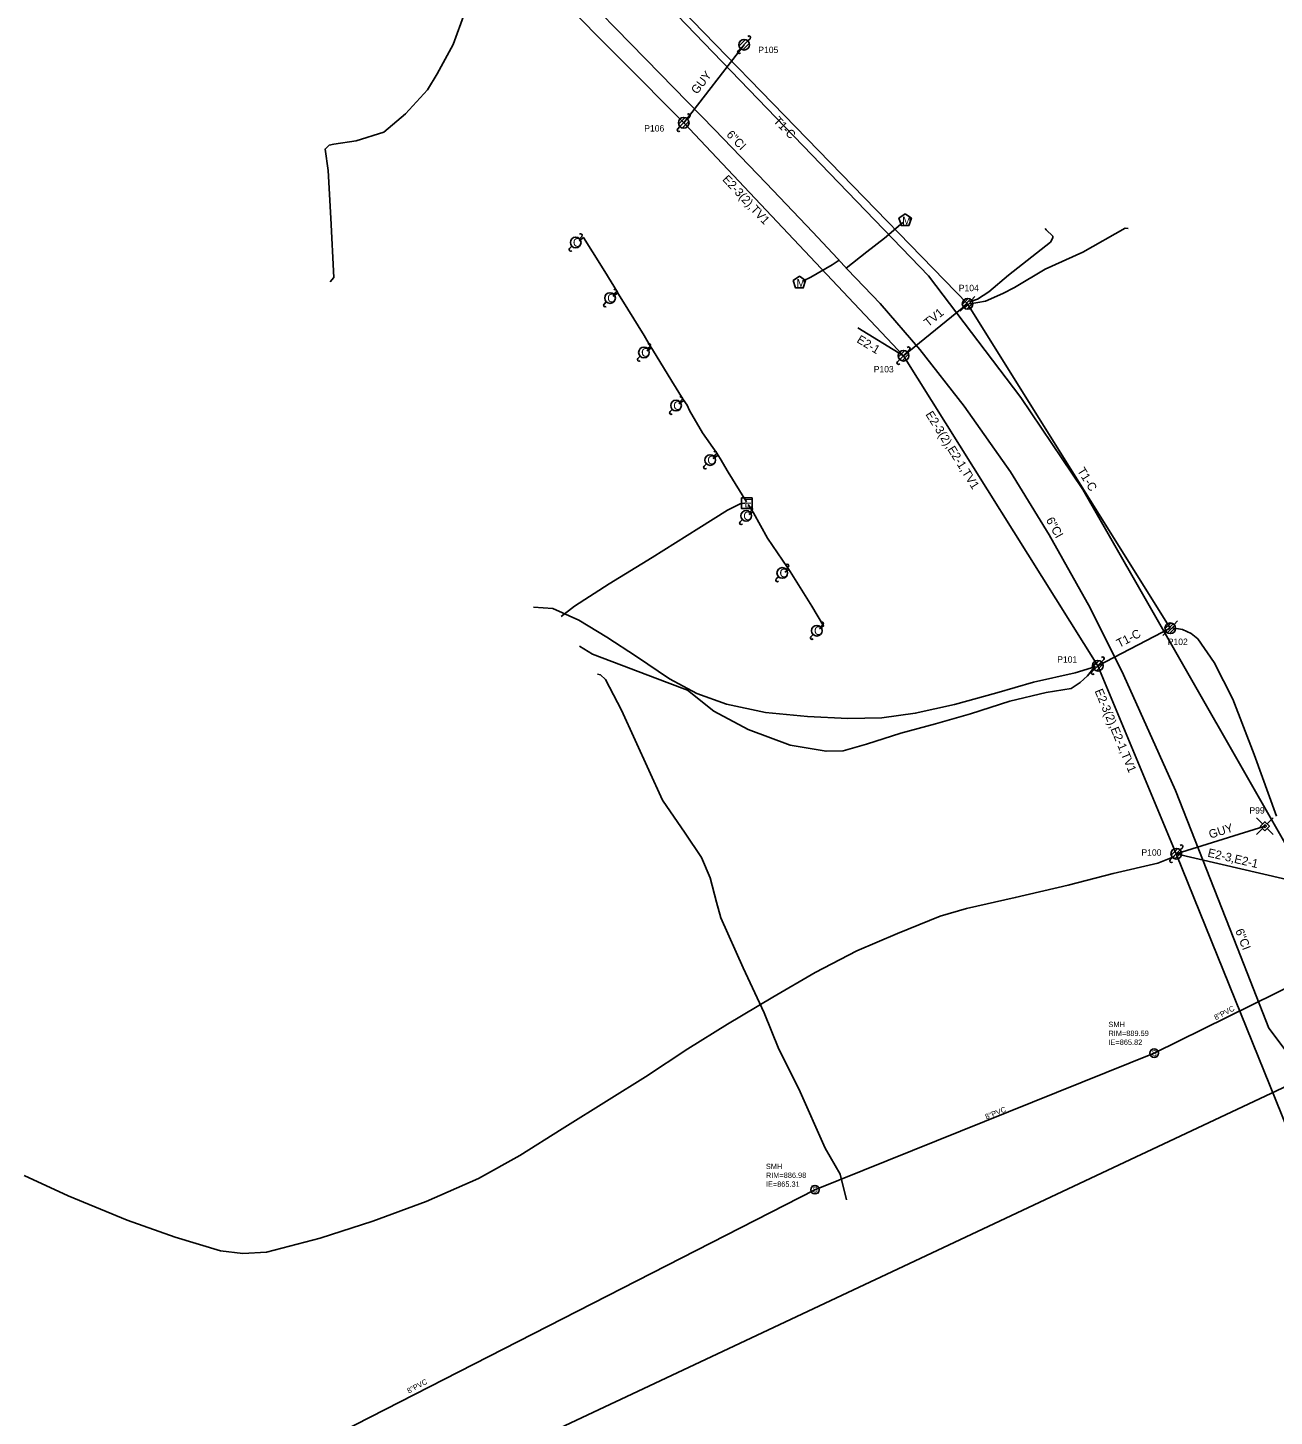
# Model space of a CAD drawing. Extents: x 1614474 to 1865144, y 1098877 to 1212550.
# Drawn here: x 1755426 to 1756010, y 1169393 to 1170044 of the extents above; entities that cross this region are included whole.
import ezdxf

# ---------------------------------------------------------------- set-up
doc = ezdxf.new("R2010")
doc.units = 0
for name, color, linetype in [('BFUSER_FIBERSPAN', 7, 'Continuous'), ('RD_EX_SU_Elec', 7, 'Continuous'), ('RD_EX_SU_H2O', 7, 'Continuous'), ('RD_EX_SU_Ovhd', 7, 'Continuous'), ('RD_EX_SU_Pole', 7, 'Continuous'), ('RD_EX_SU_Sewer', 7, 'Continuous'), ('RD_EX_SU_Telecom', 7, 'Continuous'), ('RD_EX_SU_TX_H2O', 7, 'Continuous'), ('RD_EX_SU_TX_Pole', 7, 'Continuous'), ('RD_EX_SU_TX_Sewer', 7, 'Continuous'), ('RD_EX_UT_txCode', 7, 'Continuous')]:
    doc.layers.add(name, color=color, linetype=linetype)

msp = doc.modelspace()

# ---------------------------------------------------------------- linework, layer by layer
at = {"layer": 'BFUSER_FIBERSPAN'}
msp.add_lwpolyline([(1758078.94, 1170569.49), (1756437.67, 1169746.37), (1754965.34, 1169053.6)], dxfattribs=at)
at = {"layer": 'RD_EX_SU_Elec'}
for p, q in [((1755702.73, 1169919.54), (1755700.29, 1169918.05)), ((1755718.36, 1169893.88), (1755716.17, 1169892.49)), ((1755733.63, 1169869.09), (1755731.28, 1169867.55)), ((1755749.51, 1169843.43), (1755747.2, 1169842.02)), ((1755765.88, 1169817.05), (1755763.94, 1169815.74)), ((1755782.68, 1169790.03), (1755780.92, 1169788.77))]:
    msp.add_line(p, q, dxfattribs=at)
for points in [[(1755684.46, 1169943.96), (1755686.55, 1169945.47), (1755690.71, 1169938.85), (1755696.53, 1169929.52), (1755702.44, 1169919.98), (1755703.01, 1169918.9), (1755707.36, 1169911.95), (1755714.97, 1169899.6), (1755717.94, 1169894.52), (1755718.91, 1169893.09), (1755727.93, 1169878.15), (1755733.31, 1169869.63), (1755735.09, 1169866.94), (1755736.27, 1169864.53), (1755742.27, 1169853.92), (1755748.95, 1169844.54), (1755750.51, 1169841.94), (1755754.3, 1169835.62), (1755762.89, 1169821.69)], [(1755676.08, 1169767.97), (1755682.39, 1169772.8), (1755698.54, 1169783.22), (1755718.76, 1169795.63), (1755740.54, 1169809.34), (1755754.04, 1169817.71), (1755760.01, 1169820.66), (1755762.08, 1169821.07)], [(1755763.74, 1169820.48), (1755766.13, 1169816.48), (1755772.7, 1169804.7), (1755782.19, 1169790.88), (1755783.33, 1169789.02), (1755793.45, 1169772.76), (1755799.06, 1169763.55), (1755797.19, 1169762.2)], [(1755684.66, 1169754.04), (1755690.84, 1169750.23), (1755725.82, 1169737.05), (1755735.31, 1169733.4), (1755747.58, 1169723.54), (1755763.77, 1169715.02), (1755783.44, 1169707.72), (1755800.18, 1169704.81), (1755808.23, 1169704.95), (1755819.09, 1169708.17), (1755835.24, 1169713.33), (1755851.43, 1169717.64), (1755867.91, 1169722.34), (1755886.25, 1169728.34), (1755903.35, 1169732.37), (1755915.01, 1169734.24), (1755919.17, 1169737), (1755922.6, 1169740.19), (1755926.26, 1169744.59)], [(1755693.13, 1169740.9), (1755694.52, 1169740.57), (1755696.86, 1169738.41), (1755704.43, 1169724), (1755723.64, 1169681.89), (1755734.14, 1169666.38), (1755741.88, 1169655), (1755745.97, 1169645.56), (1755748.9, 1169634.05), (1755750.96, 1169626.69), (1755761.42, 1169603.36), (1755771.14, 1169582.29), (1755778.12, 1169565.15), (1755787.43, 1169546.62), (1755799.74, 1169518.82), (1755806.76, 1169506.63), (1755809.83, 1169494.65)], [(1755424.52, 1169506.03), (1755445.15, 1169496.49), (1755472.72, 1169485.1), (1755495.28, 1169477.08), (1755516.56, 1169470.72), (1755526.98, 1169469.49), (1755538.07, 1169470.13), (1755563.21, 1169476.63), (1755587.94, 1169484.68), (1755612.91, 1169493.83), (1755637.34, 1169504.53), (1755656.67, 1169515.44), (1755676.53, 1169527.92), (1755698.61, 1169541.65), (1755715.55, 1169552.18), (1755735.48, 1169565.31), (1755754.08, 1169576.9), (1755775.19, 1169589.51), (1755795.14, 1169601.1), (1755814.55, 1169611.22), (1755833.58, 1169619.46), (1755853.58, 1169627.54), (1755865.92, 1169631.07), (1755888.79, 1169636.25), (1755913.59, 1169642.05), (1755934.73, 1169647.46), (1755955.57, 1169652.35), (1755963.38, 1169655.46)]]:
    msp.add_lwpolyline(points, dxfattribs=at)
msp.add_lwpolyline([(1755765.6, 1169823.52), (1755760.6, 1169823.52), (1755760.6, 1169818.52), (1755765.6, 1169818.52)], close=True, dxfattribs=at)
at = {"layer": 'RD_EX_SU_H2O'}
for points in [[(1755419.51, 1170324.82), (1755428.9, 1170315.01), (1755440.94, 1170302.99), (1755442.22, 1170301.65), (1755453.83, 1170289.61), (1755469.55, 1170274.72), (1755490.11, 1170254.98), (1755522.61, 1170222.9), (1755545.21, 1170201.07), (1755581.64, 1170164.83), (1755584.47, 1170162.08), (1755603.36, 1170143.23), (1755654.48, 1170091.61), (1755673.95, 1170071.98), (1755722.41, 1170022.15)], [(1755722.41, 1170022.15), (1755747.86, 1169996.13), (1755772.15, 1169970.92), (1755794.02, 1169947.98), (1755805.57, 1169935.7), (1755810.22, 1169930.6), (1755825.58, 1169914.6), (1755844.07, 1169892.99), (1755864.94, 1169866.54), (1755886.55, 1169835.77), (1755904.63, 1169806.26), (1755923.91, 1169771.92)], [(1755923.91, 1169771.92), (1755939.52, 1169740.59), (1755963.83, 1169686.41), (1755992.89, 1169612.51), (1756007.59, 1169575.08), (1756015.28, 1169564.93), (1756064.58, 1169585.92), (1756121.11, 1169611.4), (1756206.64, 1169653.11), (1756271, 1169684.14), (1756275.23, 1169686.24), (1756334.12, 1169715.1), (1756393.44, 1169745.19), (1756482.23, 1169790.32), (1756557.26, 1169827.38), (1756623.37, 1169859.51), (1756626.48, 1169861.14), (1756714.89, 1169903.8), (1756780.35, 1169935.86), (1756860.71, 1169974.61), (1756869.54, 1169979.15), (1756904.9, 1169996.7)], [(1755809.67, 1169931.2), (1755819.29, 1169938.73), (1755827.52, 1169945.25), (1755836.19, 1169952.51)], [(1755789.16, 1169925.01), (1755793.05, 1169926.98), (1755803.11, 1169932.73), (1755806.28, 1169934.92)]]:
    msp.add_lwpolyline(points, dxfattribs=at)
for points in [[(1755837.24, 1169956.61), (1755834.34, 1169954.51), (1755835.45, 1169951.1), (1755839.03, 1169951.1), (1755840.14, 1169954.51)], [(1755787.68, 1169927.44), (1755784.78, 1169925.33), (1755785.89, 1169921.92), (1755789.47, 1169921.92), (1755790.58, 1169925.33)]]:
    msp.add_lwpolyline(points, close=True, dxfattribs=at)
at = {"layer": 'RD_EX_SU_Ovhd'}
for p, q in [((1755579.05, 1170154.72), (1755733.5, 1169999.29)), ((1755667.78, 1170119.23), (1755866.5, 1169914.45)), ((1755733.5, 1169999.29), (1755761.81, 1170035.84)), ((1755866.5, 1169914.45), (1755961.43, 1169762.41)), ((1755815.1, 1169903.12), (1755836.46, 1169890.14)), ((1755836.46, 1169890.14), (1755927.48, 1169744.89)), ((1755927.48, 1169744.89), (1755961.43, 1169762.41)), ((1755927.48, 1169744.89), (1755964.26, 1169656.78)), ((1755964.26, 1169656.78), (1756005.76, 1169669.68)), ((1755964.26, 1169656.78), (1756027.03, 1169642.15)), ((1755964.26, 1169656.78), (1756076.65, 1169378.21))]:
    msp.add_line(p, q, dxfattribs=at)
for points in [[(1755733.5, 1169999.29), (1755836.46, 1169890.14)], [(1755836.46, 1169890.14), (1755866.5, 1169914.45)]]:
    msp.add_lwpolyline(points, dxfattribs=at)
at = {"layer": 'RD_EX_SU_Pole'}
for p, q in [((1755758.98, 1170033.01), (1755760.04, 1170034.07)), ((1755759.39, 1170035.19), (1755762.45, 1170038.25)), ((1755760.04, 1170034.07), (1755763.57, 1170037.61)), ((1755761.16, 1170033.42), (1755764.22, 1170036.48)), ((1755763.57, 1170037.61), (1755764.64, 1170038.67)), ((1755731.09, 1169998.65), (1755734.15, 1170001.71)), ((1755731.74, 1169997.53), (1755735.27, 1170001.06)), ((1755732.86, 1169996.88), (1755735.92, 1169999.94)), ((1755735.27, 1170001.06), (1755736.33, 1170002.12)), ((1755730.68, 1169996.47), (1755731.74, 1169997.53)), ((1755680.07, 1169940.36), (1755681.13, 1169941.43)), ((1755684.67, 1169944.96), (1755685.73, 1169946.02)), ((1755696.18, 1169914.32), (1755697.24, 1169915.38)), ((1755700.77, 1169918.92), (1755701.83, 1169919.98)), ((1755712.06, 1169888.85), (1755713.12, 1169889.91)), ((1755716.66, 1169893.44), (1755717.72, 1169894.5)), ((1755834.04, 1169889.49), (1755837.11, 1169892.56)), ((1755834.69, 1169888.37), (1755838.23, 1169891.91)), ((1755835.81, 1169887.73), (1755838.87, 1169890.79)), ((1755838.23, 1169891.91), (1755839.29, 1169892.97)), ((1755833.63, 1169887.31), (1755834.69, 1169888.37)), ((1755727.09, 1169863.94), (1755728.15, 1169865)), ((1755731.68, 1169868.53), (1755732.74, 1169869.59)), ((1755747.64, 1169842.99), (1755748.7, 1169844.05)), ((1755743.05, 1169838.4), (1755744.11, 1169839.46)), ((1755764.51, 1169816.85), (1755765.57, 1169817.91)), ((1755759.91, 1169812.26), (1755760.97, 1169813.32)), ((1755776.86, 1169785.52), (1755777.92, 1169786.58)), ((1755781.45, 1169790.12), (1755782.52, 1169791.18)), ((1755793.04, 1169758.46), (1755794.1, 1169759.52)), ((1755797.63, 1169763.05), (1755798.69, 1169764.11)), ((1755925.07, 1169744.24), (1755928.13, 1169747.31)), ((1755925.71, 1169743.12), (1755929.25, 1169746.66)), ((1755929.25, 1169746.66), (1755930.31, 1169747.72)), ((1755924.65, 1169742.06), (1755925.71, 1169743.12)), ((1755926.83, 1169742.48), (1755929.9, 1169745.54)), ((1756004.64, 1169668.64), (1756001.82, 1169665.81)), ((1756004.7, 1169670.74), (1756001.87, 1169673.57)), ((1756006.78, 1169670.8), (1756009.62, 1169673.64)), ((1756006.82, 1169668.62), (1756009.65, 1169665.79)), ((1755961.43, 1169653.95), (1755962.49, 1169655.01)), ((1755961.84, 1169656.13), (1755964.91, 1169659.19)), ((1755962.49, 1169655.01), (1755966.03, 1169658.55)), ((1755963.61, 1169654.36), (1755966.67, 1169657.43)), ((1755966.03, 1169658.55), (1755967.09, 1169659.61))]:
    msp.add_line(p, q, dxfattribs=at)
for points in [[(1756005.76, 1169667.56), (1756007.88, 1169669.68), (1756005.76, 1169671.8), (1756003.63, 1169669.68)], [(1756005.76, 1169668.97), (1756006.46, 1169669.68), (1756005.76, 1169670.39), (1756005.05, 1169669.68)]]:
    msp.add_lwpolyline(points, close=True, dxfattribs=at)
for centre in [(1755761.81, 1170035.84), (1755733.5, 1169999.29), (1755682.9, 1169943.19), (1755699, 1169917.15), (1755714.89, 1169891.67), (1755836.46, 1169890.14), (1755729.92, 1169866.77), (1755745.87, 1169841.23), (1755762.74, 1169815.08), (1755779.69, 1169788.35), (1755795.87, 1169761.29), (1755927.48, 1169744.89), (1755964.26, 1169656.78)]:
    msp.add_circle(centre, 2.5, dxfattribs=at)
for centre, start, end in [((1755764.11, 1170039.2), 315, 135), ((1755759.51, 1170032.48), 135, 315), ((1755735.8, 1170002.65), 315, 135), ((1755731.21, 1169995.94), 135, 315), ((1755685.2, 1169946.55), 315, 135), ((1755680.6, 1169939.83), 135, 315), ((1755701.3, 1169920.51), 315, 135), ((1755696.71, 1169913.79), 135, 315), ((1755717.19, 1169895.03), 315, 135), ((1755838.76, 1169893.5), 315, 135), ((1755712.59, 1169888.32), 135, 315), ((1755834.16, 1169886.78), 135, 315), ((1755732.21, 1169870.12), 315, 135), ((1755727.62, 1169863.41), 135, 315), ((1755748.17, 1169844.59), 315, 135), ((1755743.58, 1169837.87), 135, 315), ((1755765.04, 1169818.44), 315, 135), ((1755760.44, 1169811.73), 135, 315), ((1755781.98, 1169791.71), 315, 135), ((1755777.39, 1169784.99), 135, 315), ((1755798.16, 1169764.64), 315, 135), ((1755793.57, 1169757.93), 135, 315), ((1755929.78, 1169748.25), 315, 135), ((1755925.18, 1169741.53), 135, 315), ((1755966.56, 1169660.14), 315, 135), ((1755961.96, 1169653.42), 135, 315)]:
    msp.add_arc(centre, 0.75, start, end, dxfattribs=at)
at = {"layer": 'RD_EX_SU_Sewer'}
msp.add_lwpolyline([(1755472.28, 1170308.43), (1755562.01, 1170223), (1755684.15, 1170097.75), (1755848.2, 1169927.49), (1755891.42, 1169870.58), (1755920.4, 1169827.47), (1756045.49, 1169608.65)], dxfattribs=at)
for centre in [(1755953.84, 1169563.33), (1755795, 1169499.36)]:
    msp.add_circle(centre, 2, dxfattribs=at)
at = {"layer": 'RD_EX_SU_Telecom'}
for p, q in [((1755864.02, 1169914.12), (1755866.83, 1169916.93)), ((1755864.4, 1169913.09), (1755867.86, 1169916.55)), ((1755865.11, 1169912.38), (1755868.58, 1169915.85)), ((1755868.27, 1169916.22), (1755869.93, 1169917.88)), ((1755863.08, 1169911.03), (1755864.73, 1169912.68)), ((1755866.12, 1169911.98), (1755868.97, 1169914.83)), ((1755868.02, 1169912.47), (1755868.49, 1169912.93)), ((1755963.2, 1169764.18), (1755964.85, 1169765.84)), ((1755958, 1169758.99), (1755959.66, 1169760.65)), ((1755958.95, 1169762.08), (1755961.76, 1169764.89)), ((1755959.33, 1169761.05), (1755962.79, 1169764.51)), ((1755960.03, 1169760.34), (1755963.5, 1169763.81)), ((1755961.05, 1169759.94), (1755963.9, 1169762.79)), ((1755962.95, 1169760.43), (1755963.41, 1169760.89))]:
    msp.add_line(p, q, dxfattribs=at)
for points in [[(1755567.85, 1169924.8), (1755569.62, 1169926.81), (1755568.28, 1169954.57), (1755566.99, 1169976.86), (1755565.52, 1169986.95), (1755567.37, 1169988.76), (1755569.56, 1169989.18), (1755580.03, 1169990.8), (1755593.08, 1169994.88), (1755603.19, 1170003.52), (1755613.47, 1170014.77), (1755617.97, 1170022.17), (1755625.55, 1170035.96), (1755631.01, 1170050.95), (1755636.29, 1170066.08), (1755638.75, 1170072.83), (1755638.78, 1170078.26), (1755637.07, 1170082.95), (1755628.43, 1170093.71), (1755615.86, 1170108.75), (1755603.37, 1170122.6), (1755594.17, 1170134.98), (1755585.49, 1170144.68), (1755579.2, 1170154.15)], [(1755867.41, 1169915.39), (1755871.18, 1169916.7), (1755876.51, 1169920.1), (1755885.61, 1169927.91), (1755905.37, 1169943.4), (1755906.43, 1169945.34), (1755906.39, 1169946.18), (1755903.31, 1169949.1), (1755902.79, 1169949.78)], [(1755867.74, 1169914.45), (1755874.84, 1169915.67), (1755882.95, 1169919.22), (1755888.49, 1169922.12), (1755902.83, 1169930.76), (1755920.41, 1169938.67), (1755940.27, 1169949.89), (1755941.63, 1169949.79)], [(1755663.19, 1169772.29), (1755672.12, 1169771.62), (1755684.33, 1169766.18), (1755697.45, 1169758.21), (1755711.4, 1169749.13), (1755726.87, 1169738.75), (1755739.7, 1169731.9), (1755753.54, 1169726.8), (1755771.83, 1169722.95), (1755791.48, 1169721.04), (1755810.32, 1169720.14), (1755826.29, 1169720.47), (1755841.93, 1169722.6), (1755860.37, 1169726.67), (1755880.11, 1169732.12), (1755897.4, 1169737.12), (1755916.87, 1169741.55), (1755924.6, 1169743.89), (1755926.67, 1169746.37)], [(1755962.39, 1169762.61), (1755967.21, 1169761.81), (1755971.17, 1169760.01), (1755974.3, 1169757.47), (1755982, 1169746.41), (1755990.78, 1169729.17), (1756000.8, 1169703.32), (1756011.22, 1169674.31)]]:
    msp.add_lwpolyline(points, dxfattribs=at)
for centre in [(1755866.5, 1169914.45), (1755961.43, 1169762.41)]:
    msp.add_circle(centre, 2.5, dxfattribs=at)
at = {"layer": 'RD_EX_SU_TX_Sewer'}
for p, q in [((1755795, 1169499.36), (1755953.84, 1169563.33)), ((1755482.04, 1169339.36), (1755795, 1169499.36))]:
    msp.add_line(p, q, dxfattribs=at)
msp.add_lwpolyline([(1755953.84, 1169563.33), (1756045.46, 1169608.54), (1756198.37, 1169655.86)], dxfattribs=at)

# ---------------------------------------------------------------- texts
at = {"layer": 'RD_EX_SU_Elec'}
msp.add_text('E', height=4, dxfattribs=at).set_placement((1755761.89, 1169819.02))
at = {"layer": 'RD_EX_SU_H2O'}
for p in [(1755835.87, 1169951.57), (1755786.31, 1169922.4)]:
    msp.add_text('M', height=3.75, dxfattribs=at).set_placement(p)
at = {"layer": 'RD_EX_SU_Ovhd'}
for s, rotation, p in [('GUY', 52.2429, (1755739.75, 1170012.36)), ('T1-C', 314.14044, (1755775.25, 1169999.87)), ('E2-3(2),TV1', 313.09659, (1755751.36, 1169972.53)), ('TV1', 38.98199, (1755848.05, 1169903.46)), ('E2-1', 328.71224, (1755814.23, 1169896.63)), ('E2-3(2),E2-1,TV1', 302.07405, (1755846.61, 1169862.65)), ('T1-C', 301.97884, (1755917.68, 1169836.26)), ('T1-C', 27.30248, (1755937.5, 1169753.23)), ('E2-3(2),E2-1,TV1', 292.65473, (1755925.92, 1169733.06)), ('GUY', 17.27128, (1755980.18, 1169663.82)), ('E2-3,E2-1', 346.88334, (1755978.66, 1169655.47))]:
    msp.add_text(s, height=4, rotation=rotation, dxfattribs=at).set_placement(p)
at = {"layer": 'RD_EX_SU_Pole'}
for p in [(1755681.61, 1169941.19), (1755697.71, 1169915.15), (1755713.6, 1169889.67), (1755728.62, 1169864.77), (1755744.58, 1169839.23), (1755761.45, 1169813.08), (1755778.4, 1169786.35), (1755794.57, 1169759.29)]:
    msp.add_text('O', height=4, dxfattribs=at).set_placement(p)
at = {"layer": 'RD_EX_SU_Sewer'}
for p in [(1755952.81, 1169562.15), (1755793.97, 1169498.18)]:
    msp.add_text('S', height=2.5, dxfattribs=at).set_placement(p)
at = {"layer": 'RD_EX_SU_TX_H2O'}
for rotation, p in [(313.93453, (1755753.23, 1169993.44)), (299.31518, (1755903.06, 1169813.14)), (291.44252, (1755991.81, 1169620.73))]:
    msp.add_text('6"CI', height=4, rotation=rotation, dxfattribs=at).set_placement(p)
at = {"layer": 'RD_EX_SU_TX_Pole'}
for s, p in [('P105', (1755768.45, 1170031.94)), ('P106', (1755715.03, 1169995.18)), ('P104', (1755862.36, 1169920.36)), ('P103', (1755822.51, 1169882.32)), ('P102', (1755960.25, 1169754.6)), ('P101', (1755908.48, 1169746.31)), ('P99', (1755998.52, 1169675.57)), ('P100', (1755947.92, 1169655.89))]:
    msp.add_text(s, height=3, dxfattribs=at).set_placement(p)
at = {"layer": 'RD_EX_SU_TX_Sewer'}
for rotation, p in [(27.89723, (1755982.76, 1169578.72)), (21.85061, (1755875.28, 1169532.24)), (28.25354, (1755604.71, 1169403.78))]:
    msp.add_text('8"PVC', height=2.5, rotation=rotation, dxfattribs=at).set_placement(p)
for s, p in [('SMH', (1755932.47, 1169575.54)), ('RIM=889.59', (1755932.47, 1169571.38)), ('IE=865.82', (1755932.47, 1169567.21)), ('SMH', (1755772.01, 1169509.04)), ('RIM=886.98', (1755772.01, 1169504.87)), ('IE=865.31', (1755772.01, 1169500.7))]:
    msp.add_text(s, height=2.5, dxfattribs=at).set_placement(p)
at = {"layer": 'RD_EX_UT_txCode'}
for s, p in [('17065', (1755951.98, 1169564.33)), ('SMH', (1755952.55, 1169561.33)), ('18004', (1755793.13, 1169500.36)), ('SMH', (1755793.71, 1169497.36))]:
    msp.add_text(s, height=1, dxfattribs=at).set_placement(p)

doc.saveas('drawing.dxf')
